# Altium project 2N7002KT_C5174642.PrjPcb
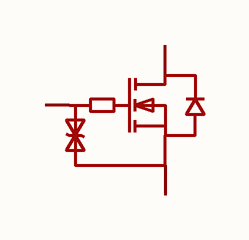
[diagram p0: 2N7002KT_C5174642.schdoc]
1 sheet, 1 parts. Net scope: global (net labels, ports and power ports of the same name join across sheets).

## Sheet 2N7002KT_C5174642.schdoc
size 127 x 101 mm

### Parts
Q?  2n7002kt_c5174642  [SOT-523-3_L1.6-W0.8-P1.00-LS1.6-BR]  (value not drawn)

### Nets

Not connected (* = marked no-connect by the designer): Q? 1(G) 2(S) 3(D)

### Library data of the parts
Q? = 2n7002kt_c5174642: 数量:1个N沟道;漏源电压(Vdss):60V;连续漏极电流(Id):300mA;导通电阻(RDS(on)):2.2Ω@10V;耗散功率(Pd):156mW;阈值电压(Vgs(th)):2V;; Manufacturer: MSKSEMI(美森科); AddInBom: yes; ModelId: 3e7fadd59d8d474faa89c2c7e0676879; ModelName: SOT-523-3P_L1.6-W0.8-H0.9-LS1.6-P0.50; ModelTransform: 63.48633,62.992,0,180,0,0,0,0,0; Number: 1个N沟道; Drain to Source Voltage: 60V; Current - Continuous Drain(Id): 300mA; Pd - Power Dissipation: 156mW; Gate Threshold Voltage (Vgs(th)): 2V; Gate Charge(Qg): 3.5nC@10V; Input Capacitance(Ciss): 15pF; Reverse Transfer Capacitance (Crss@Vds): 1pF; Output Capacitance(Coss): 2pF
